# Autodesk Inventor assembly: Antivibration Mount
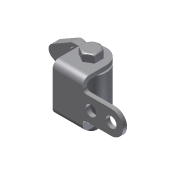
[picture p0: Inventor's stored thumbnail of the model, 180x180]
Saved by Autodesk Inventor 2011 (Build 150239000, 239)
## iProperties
Created: 2010-04
Part Number: Antivibration Mount
Document SubType Name: Assembly
Designer: CADSoft
Author: CADSoft
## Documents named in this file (6)
- C:\Users\CADSoft\Desktop\part files\c09-inv-2011-prt\Antivibration Mount\Antivibration Mount.iam
- C:\Inventor_2011\tutorials\project_Y\Yoke Plate.ipt
- C:\Inventor_2011\tutorials\project_Y\Body.ipt
- C:\Inventor_2011\tutorials\project_Y\Bushing Rubber.ipt
- C:\Inventor_2011\tutorials\project_Y\Hex Bolt.ipt
- C:\Inventor_2011\tutorials\project_Y\Nut.ipt
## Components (6 placed, 5 different names)
1. Yoke Plate:1 — Mate:1, Mate:2, Insert:3, Mate:3, Mate:5, Mate:8, Angle:1
2. Bushing Rubber:1 — Mate:1, Mate:2, Mate:7
3. Bushing Rubber:2 — Mate:5, Mate:6
4. Hex Bolt:1 — Insert:3, Mate:4, Mate:6
5. Nut:1 — Mate:3, Mate:4
6. Body:1 — Mate:7, Mate:8, Angle:1
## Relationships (10: Mate 8, Insert 1, Angle 1)
- Mate:1: Yoke Plate:1 ↔ Bushing Rubber:1
- Mate:2: Yoke Plate:1 ↔ Bushing Rubber:1
- Insert:3: Yoke Plate:1 ↔ Hex Bolt:1
- Mate:3: Yoke Plate:1 ↔ Nut:1
- Mate:4: Hex Bolt:1 ↔ Nut:1
- Mate:5: Yoke Plate:1 ↔ Bushing Rubber:2
- Mate:6: Bushing Rubber:2 ↔ Hex Bolt:1
- Mate:7: Bushing Rubber:1 ↔ Body:1
- Mate:8: Yoke Plate:1 ↔ Body:1
- Angle:1: Yoke Plate:1 ↔ Body:1
